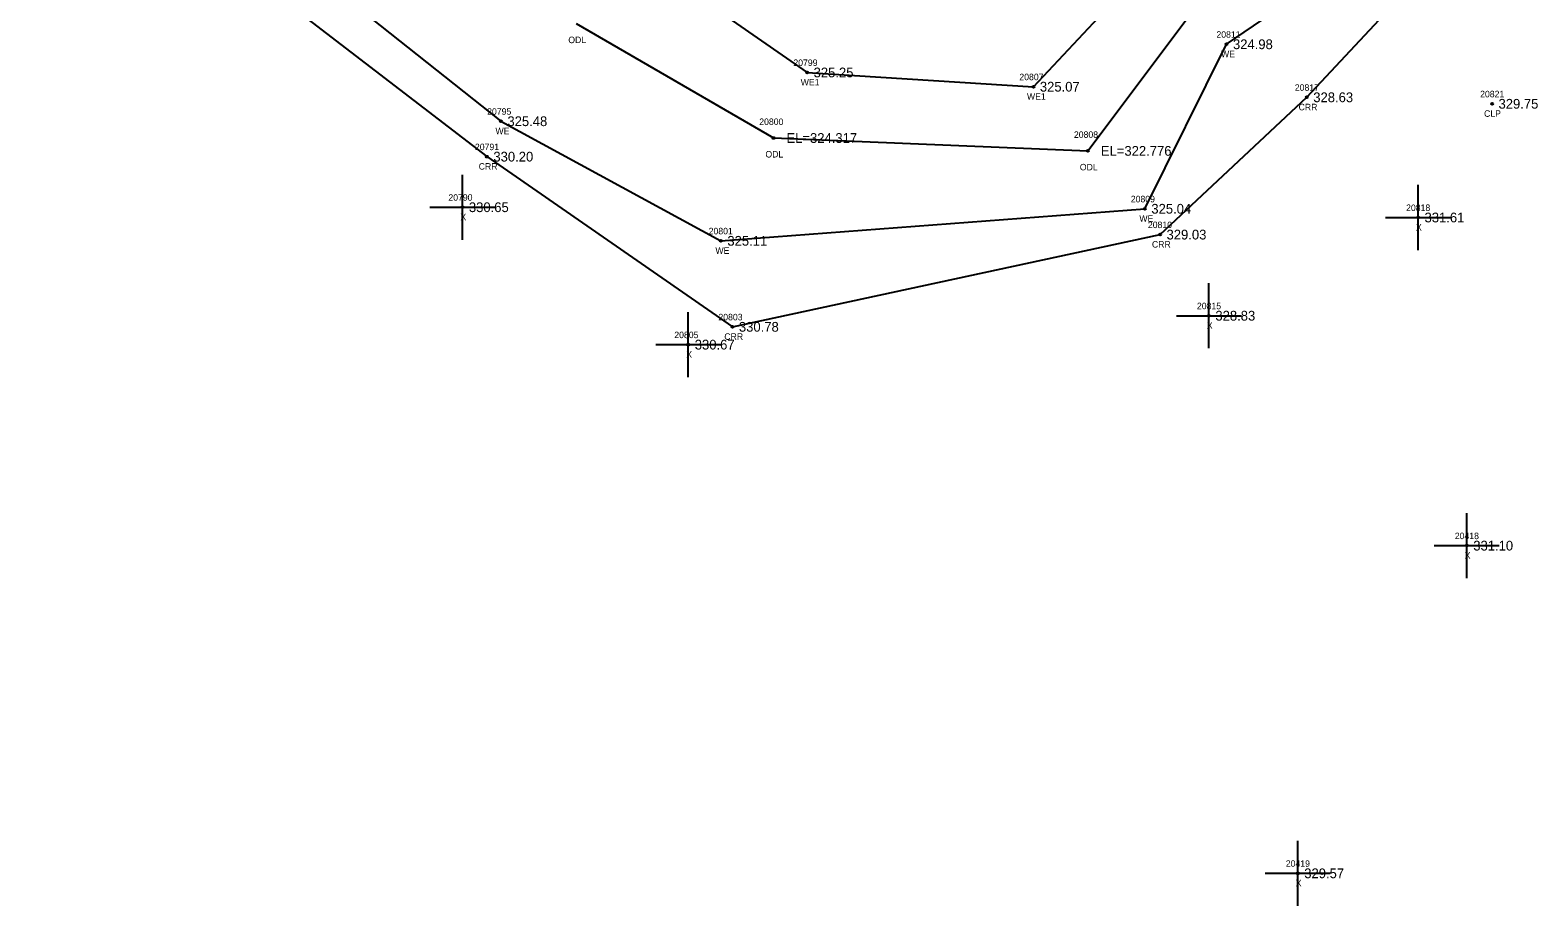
# Model space of a CAD drawing. Extents: x 2006994 to 2008877, y 1001630 to 1004414.
# Drawn here: x 2007669.1 to 2007901.2, y 1002784.1 to 1002918.8 of the extents above; entities that cross this region are included whole.
import ezdxf

# ---------------------------------------------------------------- set-up
doc = ezdxf.new("R2010")
doc.units = 0
for name, color, linetype in [('RD_EX_H2O', 7, 'Continuous'), ('RD_EX_H2O_txCode', 7, 'Continuous'), ('RD_EX_Misc', 7, 'Continuous'), ('RD_EX_Misc_txCode', 7, 'Continuous'), ('RD_EX_TX_H2O_ELEV', 7, 'Continuous'), ('RD_EX_TX_Misc_ELEV', 7, 'Continuous'), ('RD_HC_Survey_ELEV', 7, 'Continuous'), ('RD_HC_Survey_txCode', 7, 'Continuous'), ('RD_SMD_Locator', 7, 'Continuous')]:
    doc.layers.add(name, color=color, linetype=linetype)

msp = doc.modelspace()

# ---------------------------------------------------------------- linework, layer by layer
at = {"layer": 'RD_EX_H2O'}
for points in [[(2007672.91, 1002959.18), (2007741.53, 1002904.78), (2007775.39, 1002886.38), (2007840.66, 1002891.31), (2007853.23, 1002916.62), (2007885.2, 1002938.4)], [(2007669.06, 1002953.29), (2007739.37, 1002899.33), (2007777.17, 1002873.15), (2007843, 1002887.34), (2007865.59, 1002908.46), (2007889.4, 1002933.96)], [(2007762.38, 1002930.53), (2007788.67, 1002912.28), (2007823.5, 1002910.09), (2007841.22, 1002929)], [(2007753.14, 1002919.79), (2007783.49, 1002902.2), (2007831.89, 1002900.22), (2007848.89, 1002922.83)]]:
    msp.add_lwpolyline(points, dxfattribs=at)
at = {"layer": 'RD_EX_Misc'}
for p, q in [((2007735.6, 1002886.55), (2007735.6, 1002896.55)), ((2007882.72, 1002884.97), (2007882.72, 1002894.97)), ((2007730.6, 1002891.55), (2007740.6, 1002891.55)), ((2007877.72, 1002889.97), (2007887.72, 1002889.97)), ((2007850.52, 1002869.86), (2007850.52, 1002879.86)), ((2007770.37, 1002865.41), (2007770.37, 1002875.41)), ((2007845.52, 1002874.86), (2007855.52, 1002874.86)), ((2007765.37, 1002870.41), (2007775.37, 1002870.41)), ((2007890.22, 1002834.49), (2007890.22, 1002844.49)), ((2007885.22, 1002839.49), (2007895.22, 1002839.49)), ((2007864.2, 1002784.08), (2007864.2, 1002794.08)), ((2007859.2, 1002789.08), (2007869.2, 1002789.08))]:
    msp.add_line(p, q, dxfattribs=at)
at = {"layer": 'RD_SMD_Locator'}
for centre in [(2007853.23, 1002916.62), (2007788.67, 1002912.28), (2007823.5, 1002910.09), (2007865.59, 1002908.46), (2007894.11, 1002907.46), (2007741.53, 1002904.78), (2007783.49, 1002902.2), (2007739.37, 1002899.33), (2007831.89, 1002900.22), (2007735.6, 1002891.55), (2007840.66, 1002891.31), (2007882.72, 1002889.97), (2007775.39, 1002886.38), (2007843, 1002887.34), (2007850.52, 1002874.86), (2007777.17, 1002873.15), (2007770.37, 1002870.41), (2007890.22, 1002839.49), (2007864.2, 1002789.08)]:
    msp.add_circle(centre, 0.15, dxfattribs=at)

# ---------------------------------------------------------------- texts
at = {"layer": 'RD_EX_H2O_txCode'}
for s, p in [('20811', (2007851.68, 1002917.62)), ('ODL', (2007751.9, 1002916.79)), ('20799', (2007786.55, 1002913.28)), ('WE', (2007852.39, 1002914.62)), ('WE1', (2007787.68, 1002910.28)), ('20807', (2007821.34, 1002911.09)), ('WE1', (2007822.51, 1002908.09)), ('20817', (2007863.75, 1002909.46)), ('20795', (2007739.41, 1002905.78)), ('CRR', (2007864.33, 1002906.46)), ('20800', (2007781.3, 1002904.2)), ('WE', (2007740.69, 1002902.78)), ('20808', (2007829.74, 1002902.22)), ('20791', (2007737.53, 1002900.33)), ('ODL', (2007782.25, 1002899.2)), ('CRR', (2007738.11, 1002897.33)), ('ODL', (2007830.65, 1002897.22)), ('20809', (2007838.5, 1002892.31)), ('WE', (2007839.82, 1002889.31)), ('20801', (2007773.51, 1002887.38)), ('20810', (2007841.13, 1002888.34)), ('CRR', (2007841.75, 1002885.34)), ('WE', (2007774.55, 1002884.38)), ('20803', (2007775.01, 1002874.15)), ('CRR', (2007775.92, 1002871.15))]:
    msp.add_text(s, height=1, dxfattribs=at).set_placement(p)
at = {"layer": 'RD_EX_Misc_txCode'}
for s, p in [('20790', (2007733.44, 1002892.55)), ('X', (2007735.29, 1002889.55)), ('20818', (2007880.88, 1002890.97)), ('X', (2007882.4, 1002887.97)), ('20815', (2007848.68, 1002875.86)), ('20805', (2007768.22, 1002871.41)), ('X', (2007850.2, 1002872.86)), ('X', (2007770.06, 1002868.41)), ('20418', (2007888.38, 1002840.49)), ('X', (2007889.9, 1002837.49)), ('20419', (2007862.36, 1002790.08)), ('X', (2007863.88, 1002787.08))]:
    msp.add_text(s, height=1, dxfattribs=at).set_placement(p)
at = {"layer": 'RD_EX_TX_H2O_ELEV'}
for s, p in [('324.98', (2007854.23, 1002915.87)), ('325.25', (2007789.67, 1002911.53)), ('325.07', (2007824.5, 1002909.34)), ('328.63', (2007866.59, 1002907.71)), ('325.48', (2007742.53, 1002904.03)), ('EL=324.317', (2007785.49, 1002901.45)), ('330.20', (2007740.37, 1002898.58)), ('EL=322.776', (2007833.89, 1002899.47)), ('325.04', (2007841.66, 1002890.56)), ('329.03', (2007844, 1002886.59)), ('325.11', (2007776.39, 1002885.63)), ('330.78', (2007778.17, 1002872.4))]:
    msp.add_text(s, height=1.5, dxfattribs=at).set_placement(p)
at = {"layer": 'RD_EX_TX_Misc_ELEV'}
for s, p in [('330.65', (2007736.6, 1002890.8)), ('331.61', (2007883.72, 1002889.22)), ('328.83', (2007851.52, 1002874.11)), ('330.67', (2007771.37, 1002869.66)), ('331.10', (2007891.22, 1002838.74)), ('329.57', (2007865.2, 1002788.33))]:
    msp.add_text(s, height=1.5, dxfattribs=at).set_placement(p)
at = {"layer": 'RD_HC_Survey_ELEV'}
msp.add_text('329.75', height=1.5, dxfattribs=at).set_placement((2007895.11, 1002906.71))
at = {"layer": 'RD_HC_Survey_txCode'}
for s, p in [('20821', (2007892.28, 1002908.46)), ('CLP', (2007892.88, 1002905.46))]:
    msp.add_text(s, height=1, dxfattribs=at).set_placement(p)

doc.saveas('drawing.dxf')
